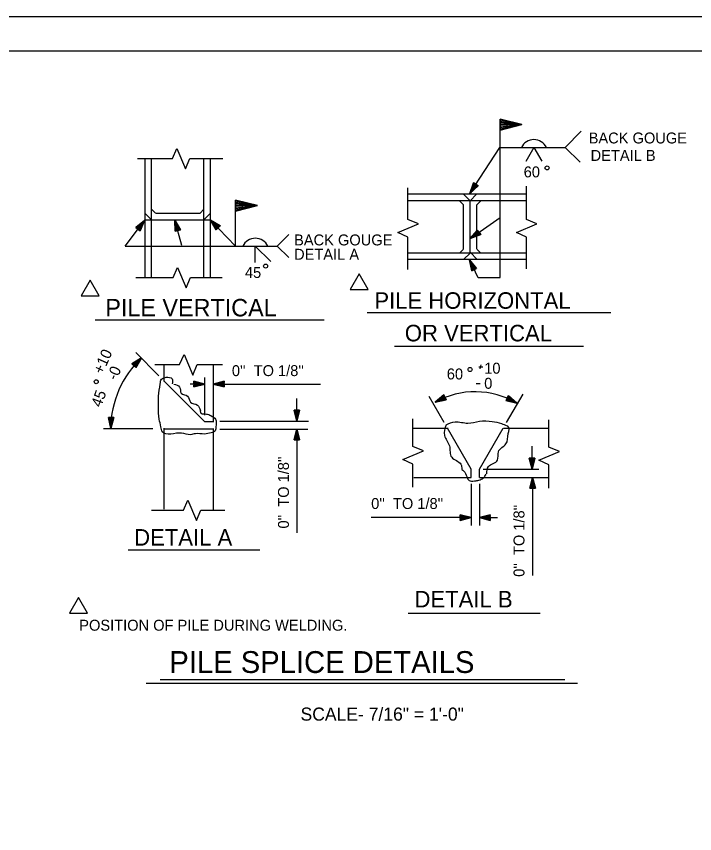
# Model space of a CAD drawing. Extents: x -41 to 251, y -169 to 237.
# Drawn here: x 27.5 to 45.29, y -139.61 to -118.18 of the extents above; entities that cross this region are included whole.
import ezdxf

# ---------------------------------------------------------------- set-up
doc = ezdxf.new("R2010")
doc.units = 0
for name, color, linetype in [('Arrowhead Terminators CELL', 7, 'Continuous'), ('Dimension Lines', 7, 'Continuous'), ('Dimension Lines CELL', 7, 'Continuous'), ('Plan Sheet CELL', 7, 'Continuous'), ('Plot Shape CELL', 7, 'Continuous'), ('Structural Steel Lines CELL', 7, 'Continuous'), ('Text CELL', 7, 'Continuous'), ('User Information Notes CELL', 7, 'Continuous')]:
    doc.layers.add(name, color=color, linetype=linetype)

msp = doc.modelspace()

# ---------------------------------------------------------------- linework, layer by layer
at = {"layer": 'Arrowhead Terminators CELL'}
for points in [[(40.185, -121.016), (40.185, -120.988), (40.757, -121.016), (40.185, -120.959), (40.185, -120.93), (40.757, -121.016), (40.185, -120.902), (40.185, -120.873), (40.757, -121.016), (40.185, -121.16), (40.185, -121.131), (40.757, -121.016), (40.185, -121.102), (40.185, -121.074), (40.757, -121.016), (40.185, -121.045), (40.185, -120.873), (40.185, -121.16), (40.757, -121.016), (40.185, -120.873)], [(39.549, -122.584), (39.561, -122.592), (39.393, -122.824), (39.573, -122.6), (39.585, -122.607), (39.393, -122.824), (39.597, -122.615), (39.609, -122.623), (39.393, -122.824), (39.489, -122.545), (39.501, -122.553), (39.393, -122.824), (39.513, -122.561), (39.525, -122.568), (39.393, -122.824), (39.537, -122.576), (39.609, -122.623), (39.489, -122.545), (39.393, -122.824), (39.609, -122.623)], [(33.253, -123.14), (33.253, -123.111), (33.826, -123.14), (33.253, -123.082), (33.253, -123.054), (33.826, -123.14), (33.253, -123.025), (33.253, -122.996), (33.826, -123.14), (33.253, -123.283), (33.253, -123.254), (33.826, -123.14), (33.253, -123.225), (33.253, -123.197), (33.826, -123.14), (33.253, -123.168), (33.253, -122.996), (33.253, -123.283), (33.826, -123.14), (33.253, -122.996)], [(30.69, -123.758), (30.678, -123.749), (30.861, -123.528), (30.667, -123.741), (30.656, -123.732), (30.861, -123.528), (30.644, -123.724), (30.633, -123.715), (30.861, -123.528), (30.747, -123.801), (30.736, -123.792), (30.861, -123.528), (30.724, -123.784), (30.713, -123.775), (30.861, -123.528), (30.701, -123.767), (30.633, -123.715), (30.747, -123.801), (30.861, -123.528), (30.633, -123.715)], [(31.739, -123.796), (31.725, -123.8), (31.663, -123.52), (31.711, -123.803), (31.697, -123.807), (31.663, -123.52), (31.684, -123.811), (31.67, -123.815), (31.663, -123.52), (31.808, -123.777), (31.794, -123.781), (31.663, -123.52), (31.78, -123.785), (31.766, -123.788), (31.663, -123.52), (31.753, -123.792), (31.67, -123.815), (31.808, -123.777), (31.663, -123.52), (31.67, -123.815)], [(32.794, -123.726), (32.784, -123.736), (32.596, -123.52), (32.773, -123.746), (32.763, -123.756), (32.596, -123.52), (32.753, -123.766), (32.743, -123.776), (32.596, -123.52), (32.846, -123.676), (32.835, -123.686), (32.596, -123.52), (32.825, -123.696), (32.815, -123.706), (32.596, -123.52), (32.804, -123.716), (32.743, -123.776), (32.846, -123.676), (32.596, -123.52), (32.743, -123.776)], [(39.636, -123.844), (39.644, -123.855), (39.402, -124.008), (39.652, -123.867), (39.661, -123.879), (39.402, -124.008), (39.669, -123.89), (39.677, -123.902), (39.402, -124.008), (39.595, -123.785), (39.603, -123.797), (39.402, -124.008), (39.611, -123.808), (39.619, -123.82), (39.402, -124.008), (39.628, -123.832), (39.677, -123.902), (39.595, -123.785), (39.402, -124.008), (39.677, -123.902)], [(39.507, -124.818), (39.494, -124.824), (39.384, -124.559), (39.481, -124.83), (39.468, -124.836), (39.384, -124.559), (39.455, -124.842), (39.442, -124.848), (39.384, -124.559), (39.571, -124.787), (39.559, -124.793), (39.384, -124.559), (39.546, -124.799), (39.533, -124.805), (39.384, -124.559), (39.52, -124.812), (39.442, -124.848), (39.571, -124.787), (39.384, -124.559), (39.442, -124.848)], [(30.585, -127.339), (30.575, -127.329), (30.783, -127.131), (30.565, -127.319), (30.554, -127.309), (30.783, -127.131), (30.544, -127.299), (30.533, -127.289), (30.783, -127.131), (30.637, -127.388), (30.627, -127.378), (30.783, -127.131), (30.616, -127.368), (30.606, -127.358), (30.783, -127.131), (30.596, -127.348), (30.533, -127.289), (30.637, -127.388), (30.783, -127.131), (30.533, -127.289)], [(32.161, -127.819), (32.161, -127.805), (32.447, -127.819), (32.161, -127.791), (32.161, -127.776), (32.447, -127.819), (32.161, -127.762), (32.161, -127.748), (32.447, -127.819), (32.161, -127.891), (32.161, -127.876), (32.447, -127.819), (32.161, -127.862), (32.161, -127.848), (32.447, -127.819), (32.161, -127.833), (32.161, -127.748), (32.161, -127.891), (32.447, -127.819), (32.161, -127.748)], [(32.948, -127.819), (32.948, -127.833), (32.662, -127.819), (32.948, -127.848), (32.948, -127.862), (32.662, -127.819), (32.948, -127.876), (32.948, -127.891), (32.662, -127.819), (32.948, -127.748), (32.948, -127.762), (32.662, -127.819), (32.948, -127.776), (32.948, -127.791), (32.662, -127.819), (32.948, -127.805), (32.948, -127.891), (32.948, -127.748), (32.662, -127.819), (32.948, -127.891)], [(38.741, -128.169), (38.747, -128.181), (38.484, -128.295), (38.754, -128.194), (38.76, -128.207), (38.484, -128.295), (38.766, -128.22), (38.773, -128.233), (38.484, -128.295), (38.709, -128.104), (38.716, -128.117), (38.484, -128.295), (38.722, -128.13), (38.728, -128.143), (38.484, -128.295), (38.735, -128.156), (38.773, -128.233), (38.709, -128.104), (38.484, -128.295), (38.773, -128.233)], [(40.372, -128.189), (40.379, -128.177), (40.626, -128.322), (40.386, -128.164), (40.392, -128.151), (40.626, -128.322), (40.399, -128.139), (40.406, -128.126), (40.626, -128.322), (40.339, -128.253), (40.346, -128.24), (40.626, -128.322), (40.353, -128.227), (40.359, -128.215), (40.626, -128.322), (40.366, -128.202), (40.406, -128.126), (40.339, -128.253), (40.626, -128.322), (40.406, -128.126)], [(34.858, -128.508), (34.873, -128.508), (34.858, -128.794), (34.887, -128.508), (34.901, -128.508), (34.858, -128.794), (34.916, -128.508), (34.93, -128.508), (34.858, -128.794), (34.787, -128.508), (34.801, -128.508), (34.858, -128.794), (34.815, -128.508), (34.83, -128.508), (34.858, -128.794), (34.844, -128.508), (34.93, -128.508), (34.787, -128.508), (34.858, -128.794), (34.93, -128.508)], [(29.99, -128.697), (30.004, -128.698), (29.978, -128.983), (30.019, -128.699), (30.033, -128.699), (29.978, -128.983), (30.047, -128.7), (30.062, -128.7), (29.978, -128.983), (29.919, -128.694), (29.933, -128.695), (29.978, -128.983), (29.947, -128.695), (29.962, -128.696), (29.978, -128.983), (29.976, -128.697), (30.062, -128.7), (29.919, -128.694), (29.978, -128.983), (30.062, -128.7)], [(34.858, -129.279), (34.844, -129.279), (34.858, -128.993), (34.83, -129.279), (34.815, -129.279), (34.858, -128.993), (34.801, -129.279), (34.787, -129.279), (34.858, -128.993), (34.93, -129.279), (34.916, -129.279), (34.858, -128.993), (34.901, -129.279), (34.887, -129.279), (34.858, -128.993), (34.873, -129.279), (34.787, -129.279), (34.93, -129.279), (34.858, -128.993), (34.787, -129.279)], [(41.023, -129.765), (41.037, -129.765), (41.023, -130.051), (41.051, -129.765), (41.066, -129.765), (41.023, -130.051), (41.08, -129.765), (41.094, -129.765), (41.023, -130.051), (40.951, -129.765), (40.966, -129.765), (41.023, -130.051), (40.98, -129.765), (40.994, -129.765), (41.023, -130.051), (41.009, -129.765), (41.094, -129.765), (40.951, -129.765), (41.023, -130.051), (41.094, -129.765)], [(41.04, -130.552), (41.026, -130.552), (41.04, -130.266), (41.011, -130.552), (40.997, -130.552), (41.04, -130.266), (40.983, -130.552), (40.969, -130.552), (41.04, -130.266), (41.112, -130.552), (41.097, -130.552), (41.04, -130.266), (41.083, -130.552), (41.069, -130.552), (41.04, -130.266), (41.054, -130.552), (40.969, -130.552), (41.112, -130.552), (41.04, -130.266), (40.969, -130.552)], [(39.142, -131.321), (39.142, -131.307), (39.428, -131.321), (39.142, -131.293), (39.142, -131.279), (39.428, -131.321), (39.142, -131.264), (39.142, -131.25), (39.428, -131.321), (39.142, -131.393), (39.142, -131.379), (39.428, -131.321), (39.142, -131.364), (39.142, -131.35), (39.428, -131.321), (39.142, -131.336), (39.142, -131.25), (39.142, -131.393), (39.428, -131.321), (39.142, -131.25)], [(39.929, -131.321), (39.929, -131.336), (39.643, -131.321), (39.929, -131.35), (39.929, -131.364), (39.643, -131.321), (39.929, -131.379), (39.929, -131.393), (39.643, -131.321), (39.929, -131.25), (39.929, -131.264), (39.643, -131.321), (39.929, -131.279), (39.929, -131.293), (39.643, -131.321), (39.929, -131.307), (39.929, -131.393), (39.929, -131.25), (39.643, -131.321), (39.929, -131.393)]]:
    msp.add_lwpolyline(points, dxfattribs=at)
at = {"layer": 'Dimension Lines'}
for p, q in [((33.769, -124.631), (33.769, -124.202)), ((33.769, -124.202), (34.173, -124.606))]:
    msp.add_line(p, q, dxfattribs=at)
for centre in [(41.073, -121.781), (33.769, -124.367)]:
    msp.add_arc(centre, 0.369, 26.6279, 153.3721, dxfattribs=at)
at = {"layer": 'Dimension Lines CELL'}
for p, q in [((40.185, -125.025), (40.185, -120.873)), ((40.185, -121.016), (40.757, -121.016)), ((41.894, -121.616), (42.315, -121.194)), ((39.393, -122.824), (40.179, -121.616)), ((40.176, -121.616), (41.894, -121.616)), ((41.073, -121.616), (40.858, -121.987)), ((41.073, -121.616), (41.282, -121.979)), ((41.894, -121.616), (42.282, -122.004)), ((33.252, -124.202), (33.253, -122.996)), ((33.253, -123.14), (33.826, -123.14)), ((30.36, -124.202), (30.861, -123.528)), ((31.845, -124.184), (31.663, -123.52)), ((32.596, -123.52), (33.252, -124.202)), ((39.402, -124.008), (40.187, -123.456)), ((34.343, -124.202), (34.647, -123.898)), ((30.36, -124.202), (33.252, -124.202)), ((33.252, -124.202), (34.343, -124.202)), ((34.343, -124.202), (34.647, -124.505)), ((39.384, -124.559), (39.606, -125.028)), ((39.611, -125.025), (40.185, -125.025)), ((31.242, -127.603), (30.635, -126.996)), ((32.447, -128.639), (32.447, -127.647)), ((32.447, -127.819), (32.062, -127.819)), ((32.662, -127.819), (35.48, -127.819)), ((40.358, -128.829), (40.787, -128.086)), ((34.858, -128.794), (34.858, -128.199)), ((38.721, -128.829), (38.327, -128.147)), ((32.839, -128.794), (35.164, -128.794)), ((31.086, -128.993), (29.792, -128.993)), ((32.839, -129.002), (35.147, -129.002)), ((34.858, -128.993), (34.858, -131.72)), ((41.023, -130.051), (41.023, -129.444)), ((39.745, -130.051), (41.202, -130.051)), ((41.04, -130.266), (41.04, -132.837)), ((39.428, -130.438), (39.428, -131.529)), ((39.643, -130.438), (39.643, -131.529)), ((39.428, -131.321), (36.807, -131.321)), ((39.643, -131.321), (40.119, -131.321))]:
    msp.add_line(p, q, dxfattribs=at)
for centre, radius, start, end in [((32.554, -129.002), 2.576, 133.4378, 179.5922), ((39.532, -130.169), 2.147, 59.3538, 119.2053)]:
    msp.add_arc(centre, radius, start, end, dxfattribs=at)
at = {"layer": 'Plan Sheet CELL'}
msp.add_line((2.412, -119.081), (75.628, -119.081), dxfattribs=at)
at = {"layer": 'Plot Shape CELL'}
msp.add_lwpolyline([(0, -118.18), (75.648, -118.18), (75.648, -168.516), (0, -168.516)], close=True, dxfattribs=at)
at = {"layer": 'Structural Steel Lines CELL'}
for p, q in [((30.682, -121.906), (31.231, -121.906)), ((30.795, -121.906), (31.363, -121.906)), ((30.88, -125.026), (30.88, -121.909)), ((31.051, -123.315), (31.051, -121.909)), ((32.245, -121.906), (32.882, -121.906)), ((32.245, -121.906), (32.917, -121.906)), ((32.422, -125.017), (32.422, -121.909)), ((32.593, -125.017), (32.593, -121.909)), ((37.77, -123.316), (37.77, -122.677)), ((37.77, -123.316), (37.77, -122.679)), ((40.877, -123.316), (40.877, -122.628)), ((40.877, -123.316), (40.877, -122.679)), ((40.863, -122.844), (37.779, -122.844)), ((39.399, -123.013), (39.227, -122.842)), ((39.401, -123.016), (39.572, -122.845)), ((40.863, -123.015), (37.779, -123.015)), ((39.226, -123.118), (39.124, -123.015)), ((39.23, -124.275), (39.23, -123.117)), ((39.401, -124.387), (39.401, -123.013)), ((39.575, -124.275), (39.575, -123.117)), ((39.578, -123.118), (39.681, -123.015)), ((31.049, -123.515), (30.877, -123.344)), ((30.88, -123.34), (30.882, -123.34)), ((31.155, -123.339), (31.051, -123.234)), ((31.051, -125.017), (31.051, -123.318)), ((31.162, -123.34), (32.32, -123.34)), ((32.319, -123.337), (32.422, -123.234)), ((32.424, -123.508), (32.596, -123.337)), ((32.591, -123.34), (32.593, -123.34)), ((30.88, -123.512), (32.593, -123.512)), ((37.77, -124.766), (37.77, -124.198)), ((40.877, -124.766), (40.877, -124.198)), ((37.77, -124.813), (37.77, -124.33)), ((39.205, -124.385), (37.779, -124.385)), ((39.228, -124.281), (39.124, -124.385)), ((40.863, -124.385), (39.208, -124.385)), ((39.401, -124.385), (39.23, -124.556)), ((39.577, -124.546), (39.406, -124.375)), ((39.577, -124.281), (39.681, -124.385)), ((40.877, -124.797), (40.877, -124.33)), ((40.863, -124.557), (37.779, -124.557)), ((30.633, -125.023), (31.248, -125.023)), ((30.812, -125.023), (31.38, -125.023)), ((32.262, -125.023), (32.899, -125.023)), ((32.262, -125.023), (32.851, -125.023)), ((31.133, -127.311), (31.42, -127.311)), ((31.182, -127.311), (31.552, -127.311)), ((31.374, -127.298), (31.374, -127.755)), ((32.434, -127.311), (32.908, -127.311)), ((32.662, -127.311), (32.662, -128.817)), ((32.447, -128.811), (31.376, -127.741)), ((37.902, -129.269), (37.902, -128.728)), ((41.468, -129.285), (41.468, -128.761)), ((31.374, -128.973), (31.374, -130.852)), ((32.662, -128.811), (32.447, -128.811)), ((32.662, -128.981), (32.662, -131.109)), ((37.902, -129.269), (37.902, -128.81)), ((37.907, -128.978), (38.822, -128.978)), ((39.428, -130.051), (38.808, -128.978)), ((39.643, -130.051), (40.265, -128.974)), ((40.272, -128.978), (41.468, -128.978)), ((32.662, -129), (31.369, -129)), ((39.428, -130.266), (39.428, -130.051)), ((39.643, -130.266), (39.643, -130.051)), ((37.902, -130.52), (37.902, -130.151)), ((37.924, -130.266), (39.428, -130.266)), ((39.643, -130.266), (41.468, -130.266)), ((39.83, -130.175), (39.832, -130.171)), ((41.468, -130.47), (41.468, -130.167)), ((37.902, -130.503), (37.902, -130.283)), ((41.468, -130.553), (41.468, -130.299)), ((31.369, -130.852), (31.369, -131.1)), ((31.051, -131.124), (31.518, -131.124)), ((31.082, -131.124), (31.65, -131.124)), ((32.532, -131.124), (32.974, -131.124))]:
    msp.add_line(p, q, dxfattribs=at)
for points in [[(31.363, -121.906), (31.595, -121.906), (31.715, -121.644), (31.939, -122.181), (32.053, -121.906), (32.245, -121.906)], [(37.77, -124.198), (37.77, -123.966), (37.508, -123.846), (38.045, -123.622), (37.77, -123.508), (37.77, -123.316)], [(40.877, -124.198), (40.877, -123.966), (40.614, -123.846), (41.151, -123.622), (40.877, -123.508), (40.877, -123.316)], [(31.38, -125.023), (31.612, -125.023), (31.732, -124.761), (31.956, -125.298), (32.069, -125.023), (32.262, -125.023)], [(31.552, -127.311), (31.784, -127.311), (31.904, -127.048), (32.128, -127.585), (32.241, -127.311), (32.434, -127.311)], [(37.902, -130.151), (37.902, -129.919), (37.64, -129.799), (38.177, -129.574), (37.902, -129.461), (37.902, -129.269)], [(41.468, -130.167), (41.468, -129.936), (41.206, -129.815), (41.743, -129.591), (41.468, -129.478), (41.468, -129.285)], [(31.65, -131.124), (31.882, -131.124), (32.002, -130.861), (32.227, -131.398), (32.34, -131.124), (32.532, -131.124)]]:
    msp.add_lwpolyline(points, dxfattribs=at)
for points in [[(32.321, -128.501), (32.347, -128.587), (32.485, -128.605), (32.606, -128.648), (32.726, -128.743), (32.735, -128.941), (32.718, -129.045), (32.614, -129.097), (32.433, -129.131), (32.2, -129.122), (32.07, -129.148), (31.837, -129.105), (31.552, -129.131), (31.328, -129.071), (31.294, -128.941), (31.25, -128.743), (31.233, -128.415), (31.233, -128.138), (31.276, -127.819), (31.311, -127.69), (31.44, -127.638)], [(31.423, -127.638), (31.587, -127.681), (31.587, -127.815)], [(31.63, -127.819), (31.785, -127.897), (31.829, -128.061), (31.993, -128.138), (32.07, -128.294), (32.252, -128.372), (32.329, -128.51)], [(38.77, -128.885), (38.727, -129.17), (38.856, -129.438), (38.917, -129.74), (39.158, -129.921), (39.184, -130.056)], [(38.77, -128.885), (39.005, -128.81), (39.342, -128.844), (39.644, -128.792), (39.981, -128.801), (40.222, -128.853), (40.368, -128.918)], [(39.841, -130.171), (39.883, -129.981), (40.117, -129.817), (40.142, -129.593), (40.341, -129.386), (40.401, -129.118), (40.393, -128.928), (40.368, -128.918)], [(39.184, -130.056), (39.279, -130.163), (39.374, -130.344), (39.512, -130.361), (39.599, -130.344), (39.719, -130.301), (39.789, -130.232), (39.823, -130.18)]]:
    msp.add_spline(points, degree=3, dxfattribs=at)
at = {"layer": 'Text CELL'}
for p, q in [((36.702, -125.94), (43.089, -125.94)), ((29.572, -126.136), (35.576, -126.136)), ((37.416, -126.826), (42.375, -126.826)), ((39.628, -127.371), (39.735, -127.371)), ((39.666, -127.422), (39.693, -127.319)), ((39.559, -127.805), (39.666, -127.805)), ((30.439, -132.166), (33.886, -132.166)), ((37.775, -133.823), (41.237, -133.823)), ((31.278, -135.565), (41.88, -135.565)), ((30.905, -135.658), (42.216, -135.658))]:
    msp.add_line(p, q, dxfattribs=at)
for points in [[(29.436, -125.093), (29.2, -125.503), (29.673, -125.503)], [(36.491, -124.932), (36.254, -125.342), (36.728, -125.342)], [(29.136, -133.419), (28.899, -133.829), (29.372, -133.829)]]:
    msp.add_lwpolyline(points, close=True, dxfattribs=at)
for centre in [(41.419, -122.153), (34.04, -124.727), (39.398, -127.438), (29.597, -127.76)]:
    msp.add_circle(centre, 0.0525, dxfattribs=at)

# ---------------------------------------------------------------- texts
for s, height, p in [('BACK GOUGE', 0.2868, (42.508, -121.512)), ('DETAIL B', 0.2868, (42.559, -121.97)), ('60', 0.2868, (40.805, -122.401)), ('BACK GOUGE', 0.2868, (34.785, -124.185)), ('DETAIL A', 0.2868, (34.785, -124.561)), ('45', 0.2868, (33.497, -125.038)), ('PILE HORIZONTAL', 0.43278, (36.89, -125.846)), ('PILE VERTICAL', 0.45797, (29.836, -126.046)), ('OR VERTICAL', 0.43278, (37.688, -126.7)), ('10', 0.2868, (39.77, -127.548)), ("0''  TO 1/8''", 0.28625, (33.155, -127.611)), ('60', 0.2868, (38.789, -127.698)), ('0', 0.287, (39.77, -127.943)), ("0''  TO 1/8''", 0.28625, (36.807, -131.095)), ('DETAIL A', 0.4328, (30.592, -132.055)), ('DETAIL B', 0.4328, (37.942, -133.676)), ('POSITION OF PILE DURING WELDING.', 0.28676, (29.153, -134.286)), ('PILE SPLICE DETAILS', 0.5725, (31.515, -135.394))]:
    msp.add_text(s, height=height, dxfattribs=at).set_placement(p)
for s, height, rotation, p in [('+10', 0.2868, 65.994, (29.764, -127.583)), ('-0', 0.2868, 66.0065, (30.125, -127.744)), ('45', 0.2868, 69.9982, (29.723, -128.447)), ("0''  TO 1/8''", 0.28625, 90, (34.65, -131.607)), ("0''  TO 1/8''", 0.28625, 90, (40.825, -132.873))]:
    msp.add_text(s, height=height, rotation=rotation, dxfattribs=at).set_placement(p)
at = {"layer": 'User Information Notes CELL'}
msp.add_text('SCALE- 7/16" = 1\'-0"', height=0.34348, dxfattribs=at).set_placement((34.955, -136.644))

doc.saveas('drawing.dxf')
